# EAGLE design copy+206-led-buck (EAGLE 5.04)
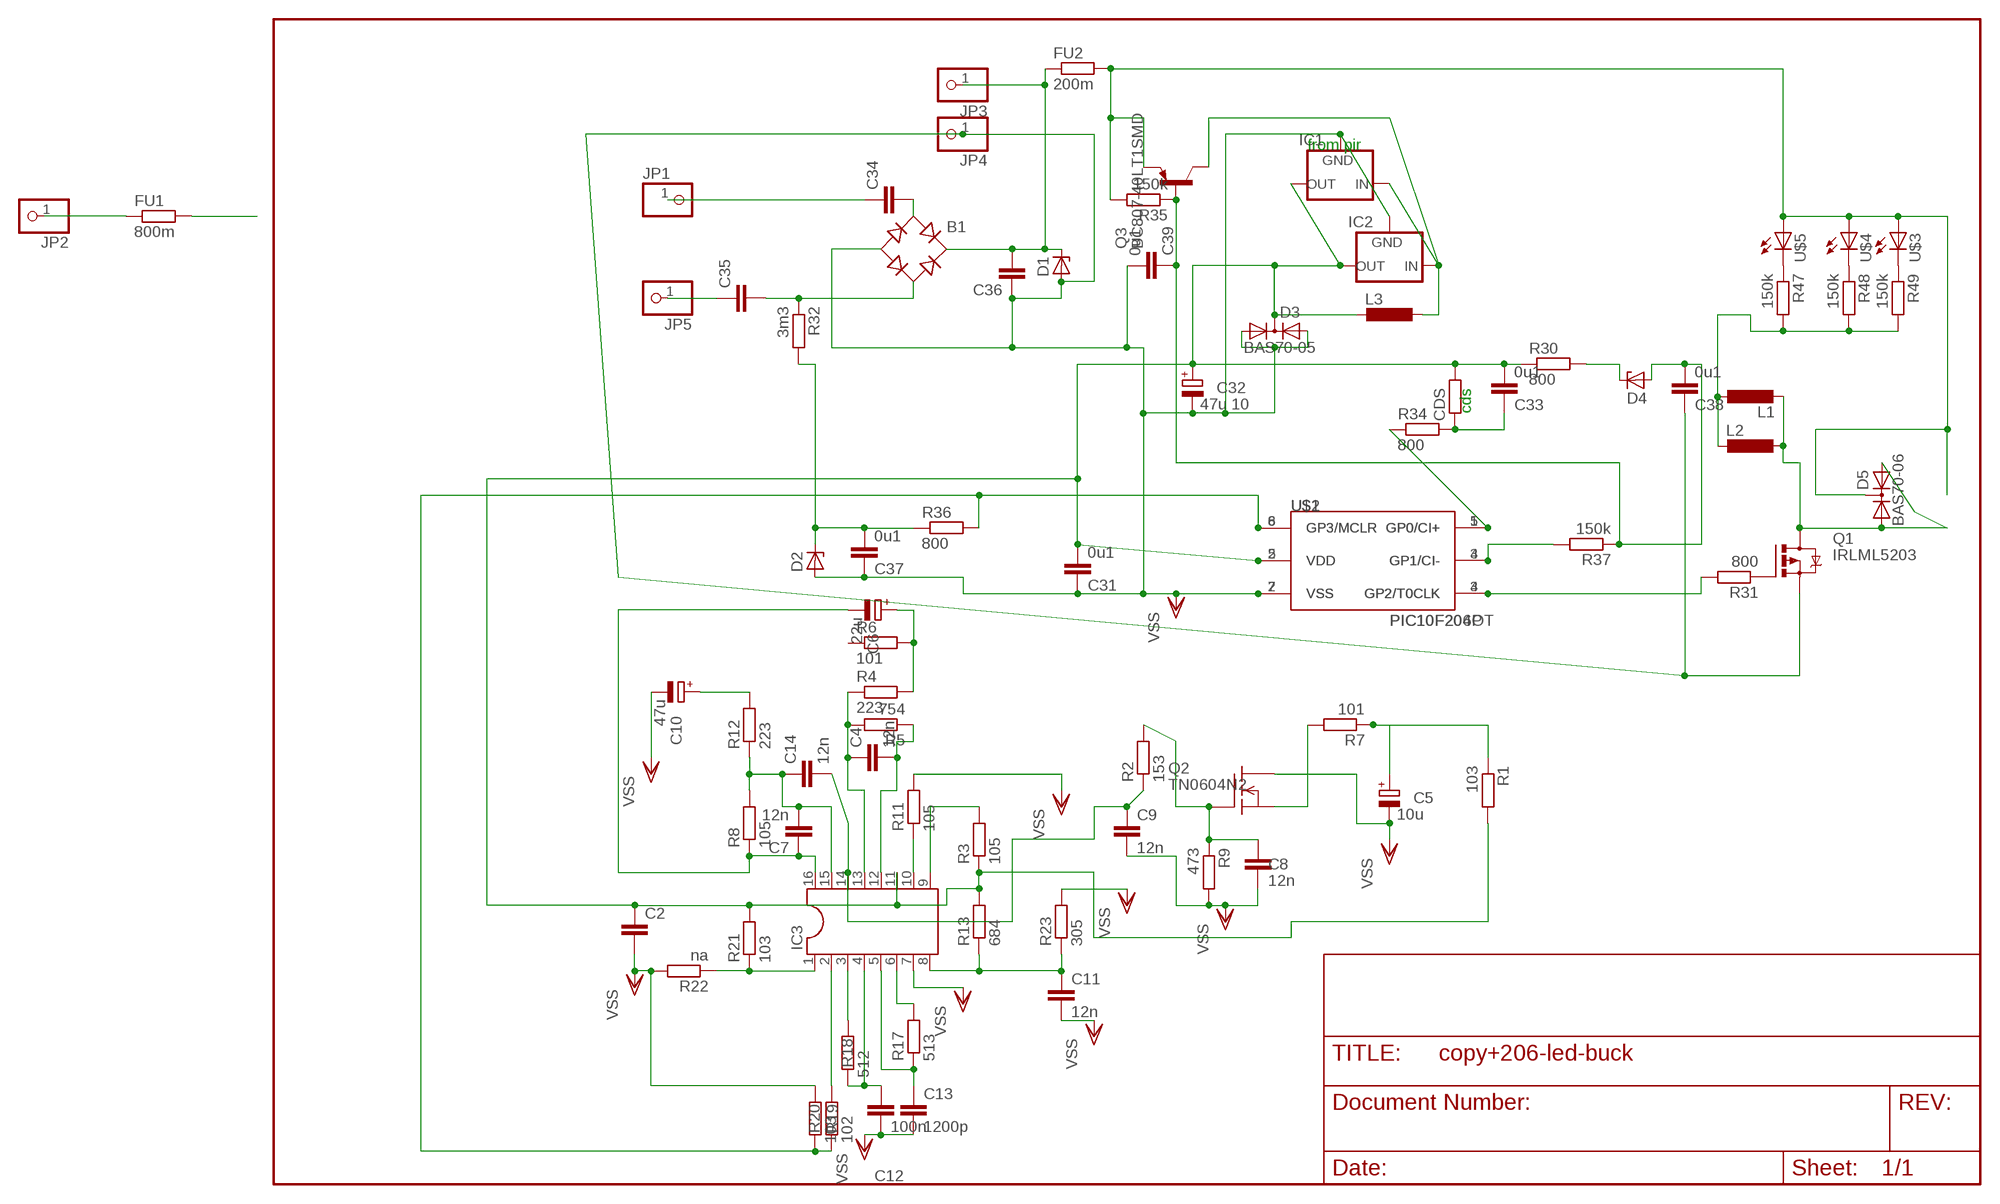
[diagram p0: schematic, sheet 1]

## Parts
B1  RB1A  [RB1A]
C2  C-EUC0805  [C0805]
C4  12n  C-EUC0805  [C0805]
C5  10u  CPOL-EUE2.5-5  [E2,5-5]
C6  22u  CPOL-EUE2.5-5  [E2,5-5]
C7  12n  C-EUC0805  [C0805]
C8  12n  C-EUC0805  [C0805]
C9  12n  C-EUC0805  [C0805]
C10  47u  CPOL-EUE2.5-5  [E2,5-5]
C11  12n  C-EUC0805  [C0805]
C12  100n  C-EUC0805  [C0805]
C13  1200p  C-EUC0805  [C0805]
C14  12n  C-EUC0805  [C0805]
C31  0u1  C-EUC1206  [C1206]
C32  47u 10  CPOL-EUE2.5-5  [E2,5-5]
C33  0u1  C-EUC1206  [C1206]
C34  C-EU050-025X075  [C050-025X075]
C35  C-EU050-025X075  [C050-025X075]
C36  C-EU050-025X075  [C050-025X075]
C37  0u1  C-EUC1206  [C1206]
C38  0u1  C-EUC1206  [C1206]
C39  0u1  C-EUC1206  [C1206]
CDS  R-EU_0207/5V  [0207/5V]
D1  ZENER-DIODEZD-7.5  [ZDIO-7.5]
D2  ZENER-DIODESOT23  [SOT23]
D3  BAS70-05  [SOT23]
D4  ZENER-DIODESOT23  [SOT23]
D5  BAS70-06  [SOT23]
FU1  800m  R-EU_0204/5  [0204/5]
FU2  200m  R-EU_0204/5  [0204/5]
IC1  XC63FPT  [TO92]
IC2  XC63FPP  [SOT89R]
IC3  DIL16SO16  [SO16]
JP1  PINHD-1X1  [1X01]
JP2  PINHD-1X1  [1X01]
JP3  PINHD-1X1  [1X01]
JP4  PINHD-1X1  [1X01]
JP5  PINHD-1X1  [1X01]
L1  L-EUL5650M  [L5650M]
L2  L-EU0207/7  [0207/7]
L3  L-EU0204V  [0204V]
Q1  IRLML5203  [MICRO3]
Q2  TN0604N2  [TO-39]
Q3  BC807-40LT1SMD  [SOT23-BEC]
R1  103  R-EU_R0805  [R0805]
R2  153  R-EU_R0805  [R0805]
R3  105  R-EU_R0805  [R0805]
R4  223  R-EU_R0805  [R0805]
R5  754  R-EU_R0805  [R0805]
R6  101  R-EU_R0805  [R0805]
R7  101  R-EU_R0805  [R0805]
R8  105  R-EU_R0805  [R0805]
R9  473  R-EU_R0805  [R0805]
R11  105  R-EU_R0805  [R0805]
R12  223  R-EU_R0805  [R0805]
R13  684  R-EU_R0805  [R0805]
R17  513  R-EU_R0805  [R0805]
R18  512  R-EU_R0805  [R0805]
R19  102  R-EU_R0805  [R0805]
R20  103  R-EU_R0805  [R0805]
R21  103  R-EU_R0805  [R0805]
R22  na  R-EU_R0805  [R0805]
R23  305  R-EU_R0805  [R0805]
R30  800  R-EU_R1206  [R1206]
R31  800  R-EU_R1206  [R1206]
R32  3m3  R-EU_R1206  [R1206]
R34  800  R-EU_R1206  [R1206]
R35  150k  R-EU_R0805  [R0805]
R36  800  R-EU_R1206  [R1206]
R37  150k  R-EU_R1206  [R1206]
R47  150k  R-EU_R1206  [R1206]
R48  150k  R-EU_R1206  [R1206]
R49  150k  R-EU_R1206  [R1206]
U$1  PIC10F206P  [DIL8]
U$2  PIC10F204OT  [SOT23-6]
U$3  LED5MM  [LED5MM]
U$4  LED5MM  [LED5MM]
U$5  LED5MM  [LED5MM]

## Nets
N$1: B1.+ C36.2 D1.C FU2.1 JP3.1
N$4: FU1.1 JP2.1
N$6: D4.3(C) R30.2
N$7: D5.3(C) FU2.2 Q3.E R35.2 U$3.A U$4.A U$5.A
N$8: C38.2 C39.1 D4.1(A) Q3.B R35.1 R37.1
N$9: FU1.2
N$10: Q1.1(G) R31.1
N$11: IC3.1 R21.1 R22.1
N$12: R19.1 R20.1 R36.2 U$1.8(GP3/MCLR) U$2.6(GP3/MCLR)
N$13: R37.2 U$1.4(GP1/CI-) U$2.3(GP1/CI-)
N$14: R31.2 U$1.3(GP2/T0CLK) U$2.4(GP2/T0CLK)
N$15: IC1.2(IN) IC2.2(IN) L3.1 Q3.C
N$16: C37.2 D2.3(C) R32.2 R36.1
N$17: C35.1 JP5.1
N$18: B1.AC2 C35.2 R32.1
N$20: C34.1 JP1.1
N$22: L1.1 L2.2 R47.2 R48.2 R49.2
N$23: C33.1 CDS.1 R34.2
N$24: IC3.2 R19.2
N$25: C12.1 IC3.4 R18.1
N$26: D5.1(A1) D5.2(A2) L1.2 L2.1 Q1.3(D)
N$27: IC3.3 R18.2
N$28: C11.1 IC3.8 R13.1 R23.1
N$29: R34.1 U$1.5(GP0/CI+) U$2.1(GP0/CI+)
N$30: C13.1 IC3.5 R17.1
N$31: IC3.6 R17.2
N$32: IC3.10 R11.1
N$33: B1.AC1 C34.2
N$34: C4.2 IC3.12 R5.1
N$35: C4.1 IC3.13 R4.1 R5.2
N$36: IC3.9 R3.2
N$37: C6.+ R4.2 R6.2
N$38: R47.1 U$5.K(C)
N$39: C9.1 C14.2 IC3.14 R2.1
N$40: C7.2 C14.1 IC3.15 R8.2 R12.1
N$41: C6.- C7.1 IC3.16 R8.1
N$42: Q2.1(S) R7.2
N$43: C5.+ R1.1 R7.1
N$44: C10.+ R12.2
N$46: C8.1 Q2.2(G) R2.2 R9.1
N$54: R48.1 U$4.K(C)
N$55: R49.1 U$3.K(C)
V2CC: C2.1 C31.2 C32.+ C33.2 CDS.2 D3.3(C) IC1.3(OUT) IC2.3(OUT) IC3.11 L3.2 R1.2 R3.1 R13.2 R21.2 R30.1 U$1.2(VDD) U$2.5(VDD)
VSS: B1.- C2.2 C5.- C8.2 C9.2 C10.- C11.2 C12.2 C13.2 C31.1 C32.- C36.1 C37.1 C38.1 C39.2 D1.A D2.1(A) D3.1(A1) D3.2(A2) IC1.1(GND) IC2.1(GND) IC3.7 JP4.1 Q1.2(S) Q2.3(D) R9.2 R11.2 R20.2 R22.2 R23.2 U$1.7(VSS) U$2.2(VSS)
Unconnected: R6.1

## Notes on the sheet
- from pir
- cds

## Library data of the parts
B1 = rectifier:RB1A: RECTIFIER 1 A
C2 C4 C7-C9 C11-C14 = rcl-2:C-EU: CAPACITOR, European symbol
C5 C6 C10 C32 = rcl:CPOL-EU: POLARIZED CAPACITOR, European symbol
C31 C33-C39 = rcl:C-EU: CAPACITOR, European symbol
CDS = rcl(2):R-EU_: RESISTOR, European symbol
D1 D2 D4 = diode-1:ZENER-DIODE: Z-Diode
D3 = diode-1:BAS70-05: Silicon Schottky Diodes General-purpose diode for high-speed switching
D5 = diode-1:BAS70-06: Silicon Schottky Diodes General-purpose diode for high-speed switching
FU1 FU2 R30-R32 R34-R37 R47-R49 = rcl:R-EU_: RESISTOR, European symbol
IC1 IC2 = v-reg:XC63FP: Positiv Voltage Regulators www.torex.co.jp/english/product/pro02/pdf/0201_xc62fp.pdf
IC3 = ic-package:DIL16: Dual In Line / Socket
JP1-JP5 = pinhead:PINHD-1X1: PIN HEADER
L1 = rcl-2:L-EU: INDUCTOR, European symbol
L2 L3 = rcl:L-EU: INDUCTOR, European symbol
Q1 = transistor-power:IRLML5203: HEXFET P-Channel Power MOSFET
Q2 = transistor-fet:TN0604N2: N-Channel Enhancement MOSFET 40V; 4A; 0,85Ohm
Q3 = transistor-pnp:BC807*: PNP Transistror
R1-R9 R11-R13 R17-R23 = rcl-2:R-EU_: RESISTOR, European symbol
U$1 U$2 = microchip-3:PIC10F2*: uPC nW 0,25/0,5k Program Flash memory Comparator
U$3-U$5 = led(3):LED: LED

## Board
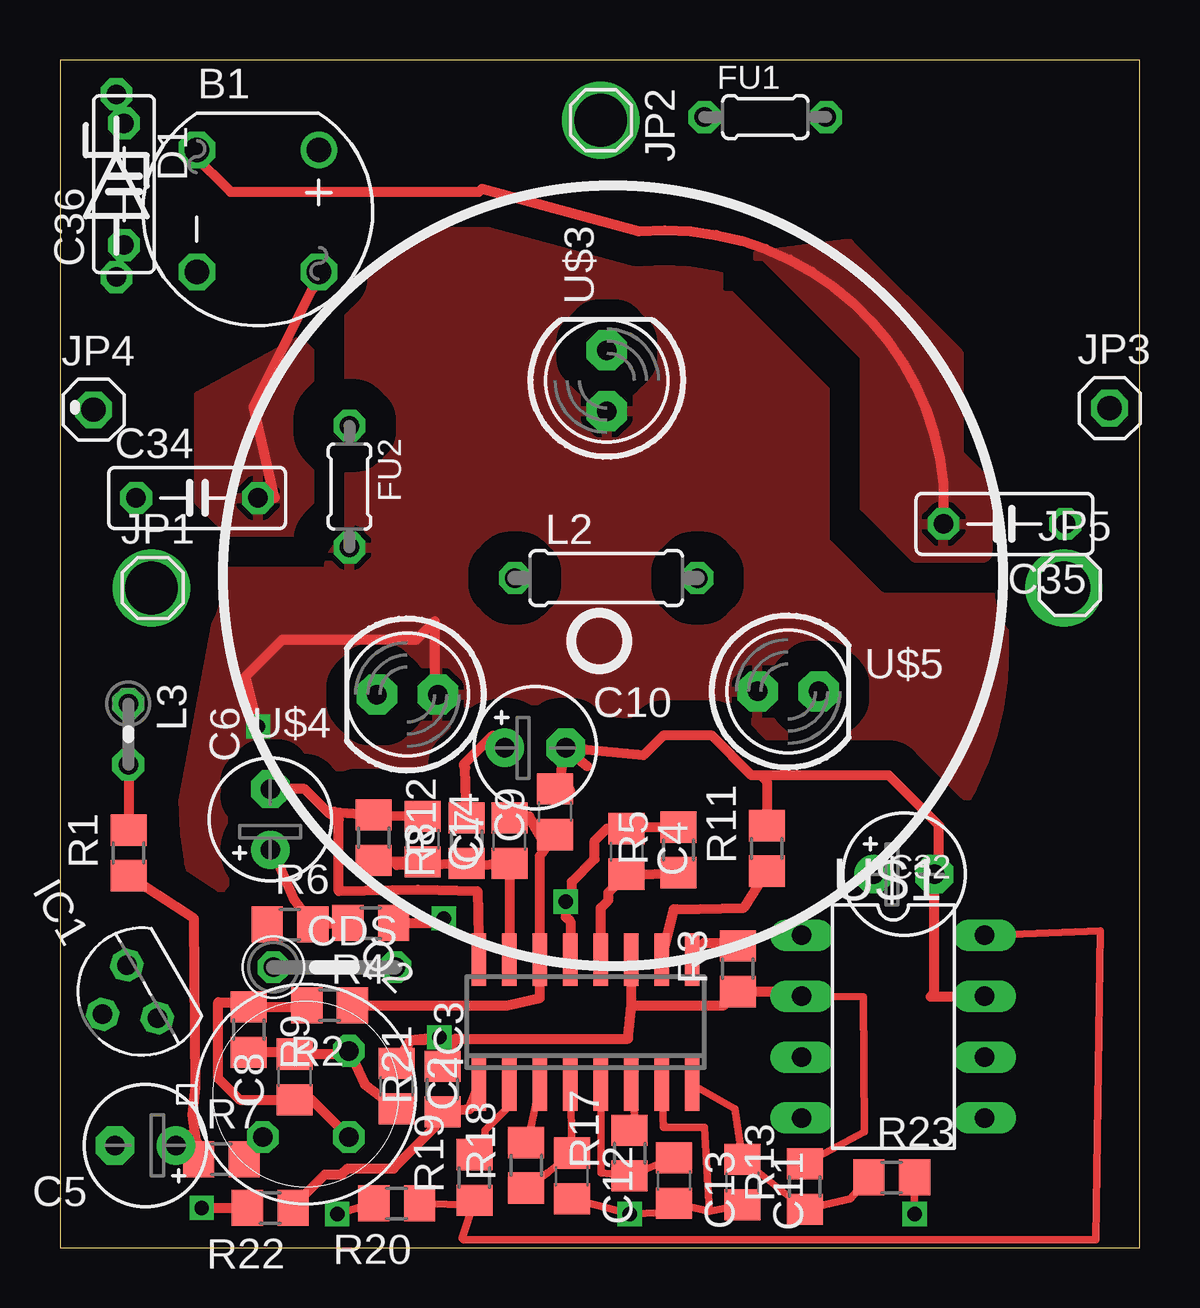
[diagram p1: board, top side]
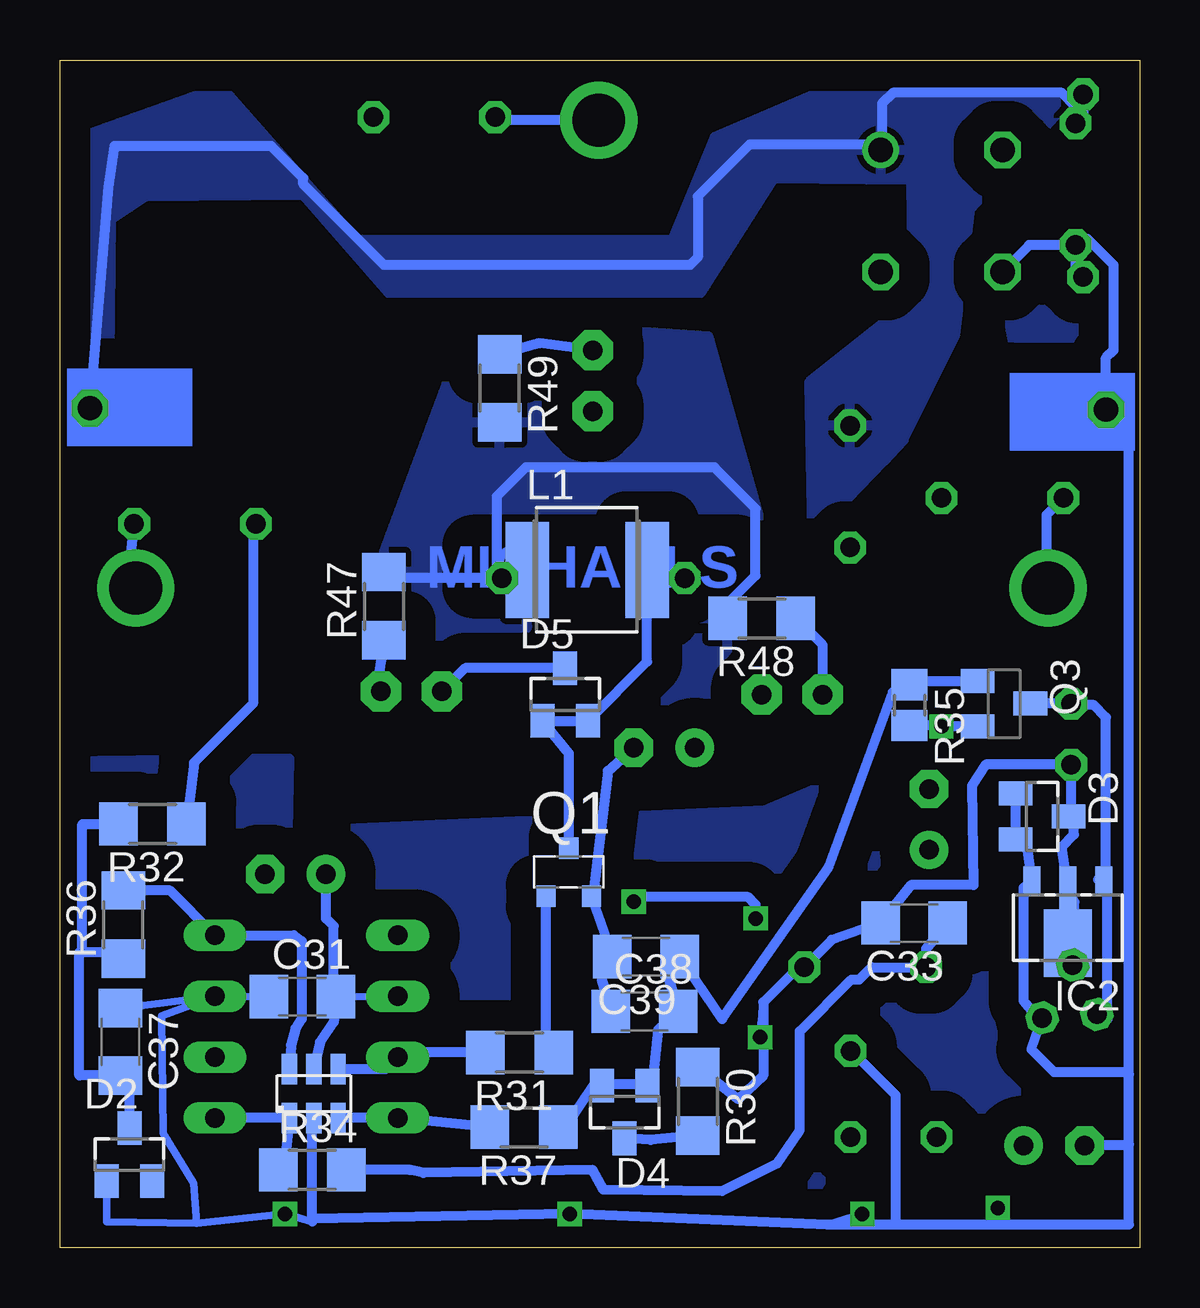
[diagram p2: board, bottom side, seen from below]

Size 45 x 49.5 mm. Coordinates in mm from the lower left corner, seen from the top.
Outline: 0,0 45,0 45,49.5 0,49.5 0,0
Copper layers (1*16): Top 0.035mm / dielectric 1.5mm / Bottom 0.035mm
Design rules "default": minimum track width 10mil, minimum drill 24mil, track to track 8mil, track to pad 8mil, pad to pad 8mil, via to via 8mil, smd to smd 8mil, copper to edge 40mil, drill to drill 8mil, minimum pad ring 10mil, minimum via ring 8mil, stop-mask expansion 4mil, vias tented up to drill 0mil, thermal gap 10mil

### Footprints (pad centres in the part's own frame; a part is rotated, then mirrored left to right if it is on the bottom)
RB1A = drill 1.016 round: + -2.54,2.54 | drill 1.016 octagon: - 2.54,-2.54; AC1 2.54,2.54; AC2 -2.54,-2.54
C0805 = smd 1.3 x 1.5: 1 -0.95,0; 2 0.95,0
E2,5-5 = drill 0.813 pad 1.6 round: + -1.27,0 | drill 0.813 pad 1.6 octagon: - 1.27,0
C1206 = smd 1.6 x 1.8: 1 -1.4,0; 2 1.4,0
C050-025X075 = drill 0.813 octagon: 1 -2.54,0; 2 2.54,0
0207/5V = drill 0.813 octagon: 1 -2.54,0; 2 2.54,0
ZDIO-7.5 = drill 0.813 octagon: A 3.81,0; C -3.81,0
SOT23 = smd 1 x 1.4: 1 -0.95,-1.1; 2 0.95,-1.1; 3 0,1.1
0204/5 = drill 0.813 octagon: 1 -2.54,0; 2 2.54,0
TO92 = drill 0.813 octagon: 1 -1.27,0; 2 0,1.905; 3 1.27,0
SOT89R = smd 0.7 x 1.1: 1 1.5,-1.75; 2 -1.5,-1.75 | smd 0.7 x 1.8: 3 0,-1.4 | smd 2 x 2.8: 4 0,0.9
SO16 = smd 0.6 x 2.2: 1 -4.445,-2.6; 2 -3.175,-2.6; 3 -1.905,-2.6; 4 -0.635,-2.6; 5 0.635,-2.6; 6 1.905,-2.6; 7 3.175,-2.6; 8 4.445,-2.6; 9 4.445,2.6; 10 3.175,2.6; 11 1.905,2.6; 12 0.635,2.6; 13 -0.635,2.6; 14 -1.905,2.6; 15 -3.175,2.6; 16 -4.445,2.6
1X01 = drill 1.016 octagon: 1 0,0
L5650M = smd 1.8 x 4: 1 -2.5,0; 2 2.5,0
0207/7 = drill 0.813 octagon: 1 -3.81,0; 2 3.81,0
0204V = drill 0.813 octagon: 1 -1.27,0; 2 1.27,0
MICRO3 = smd 0.8 x 0.9: 1 -0.95,-1; 2 0.95,-1; 3 0,1
TO-39 = drill 0.813 octagon: 1 0,-2.54; 2 2.54,0; 3 0,2.54
SOT23-BEC = smd 1 x 1.4: B -0.95,-1.1; C 0,1.1; E 0.95,-1.1
R0805 = smd 1.3 x 1.5: 1 -0.95,0; 2 0.95,0
R1206 = smd 1.6 x 1.803: 1 -1.422,0; 2 1.422,0
R0805' = smd 1.3 x 1.5: 1 -0.85,0; 2 0.85,0
DIL8 = drill 0.813 long: 1 -3.81,-3.81; 2 -1.27,-3.81; 3 1.27,-3.81; 4 3.81,-3.81; 5 3.81,3.81; 6 1.27,3.81; 7 -1.27,3.81; 8 -3.81,3.81
SOT23-6 = smd 0.635 x 1.27: 1 -1.016,-1.016; 2 0,-1.016; 3 1.016,-1.016; 4 1.016,1.016; 5 0,1.016; 6 -1.016,1.016
LED5MM = drill 0.813 pad 1.676 octagon: A -1.27,0; K 1.27,0

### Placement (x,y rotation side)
B1  8.25,43.21 270 top
C2  14.03,6.73 270 top
C4  23.62,16.51 270 top
C5  3.56,4.25 180 top
C6  8.76,17.84 90 top
C7  15.11,17.02 270 top
C8  9.78,7.11 90 top
C9  20.64,18.16 90 top
C10  19.81,20.83 0 top
C11  28.45,2.73 270 top
C12  21.34,2.98 270 top
C13  25.59,2.79 270 top
C14  18.73,16.95 90 top
C31  34.89,10.46 0 bottom
C32  35.18,15.56 0 top
C33  9.4,13.53 180 bottom
C34  5.71,31.24 0 top
C35  39.37,30.16 180 top
C36  2.67,44.32 90 top
C37  42.48,8.57 270 bottom
C38  20.64,9.84 0 bottom
C39  20.57,12.13 180 bottom
CDS  11.43,11.68 0 top
D1  2.35,44.26 270 top
D2  42.1,3.87 0 bottom
D3  4.06,17.97 270 bottom
D4  21.46,5.65 180 bottom
D5  23.94,23.05 0 bottom
FU1  29.4,47.12 0 top
FU2  12.07,31.72 270 top
IC1  3.42,10.67 120 top
IC2  2.98,13.59 180 bottom
IC3  21.91,9.4 0 top
JP1  3.87,27.5 0 top
JP2  22.54,46.99 270 top
JP3  43.75,34.99 0 top
JP4  1.4,34.92 0 top
JP5  42.1,27.62 0 top
L1  23.02,28.25 0 bottom
L2  22.77,27.91 0 top
L3  2.85,21.4 270 top
Q1  23.79,15.65 0 bottom
Q2  10.25,6.4 315 top
Q3  5.65,22.67 270 bottom
R1  2.86,16.45 90 top
R2  11.24,10.1 180 top
R3  28.26,11.62 90 top
R4  12.95,13.53 180 top
R5  25.78,16.57 90 top
R6  9.59,13.46 0 top
R7  6.73,3.68 0 top
R8  13.08,17.08 270 top
R9  7.87,9.08 270 top
R11  29.46,16.64 90 top
R12  16.95,16.95 90 top
R13  31.05,2.54 90 top
R17  23.75,3.94 90 top
R18  19.43,3.43 90 top
R19  17.27,2.92 90 top
R20  14.03,1.84 180 top
R21  15.94,6.6 90 top
R22  8.76,1.65 180 top
R23  34.67,2.92 0 top
R30  18.41,6.1 270 bottom
R31  25.84,8.13 180 bottom
R32  41.15,17.65 180 bottom
R34  34.48,3.24 0 bottom
R35  150k  [R0805']  9.59,22.61 270 bottom
R36  42.35,13.46 90 bottom
R37  25.65,5.02 180 bottom
R47  31.5,26.73 90 bottom
R48  15.75,26.23 180 bottom
R49  26.67,35.81 270 bottom
U$1  34.73,9.21 270 top
U$2  34.42,6.41 0 bottom
U$3  22.8,36.13 90 top
U$4  14.48,23.05 180 top
U$5  30.35,23.18 0 top

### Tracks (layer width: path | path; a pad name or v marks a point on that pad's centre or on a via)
GND
  pour Bottom (isolate 1.27, rank 5): 0.95,42.93 6.22,42.8 5.21,37.27 1.91,33.02 1.78,22.61 5.78,22.42 15.62,18.22 35.5,17.34 35.43,20.38 45.02,20.26 44.64,0.32 -0.06,0.25
N$1
  Bottom 0.406: JP3.1 42.99,44.2 42.74,45.91 36.2,45.91 34.86,44.58 34.86,44.32 31.5,40.96 18.73,40.96 18.41,41.27 18.41,43.81 16.26,45.97 11.2,45.97 B1.+ 10.73,45.8 10.73,47.69 10.29,48.13 3.24,48.13 2.67,47.56 C36.2 2.35,47.18 D1.C
  pour Bottom (isolate 1.27, rank 2): 1.52,49.34 9.97,49.59 17.72,46.29 19.49,42 32.64,42 38.29,48.39 44.89,46.04 44.7,36.96 42.93,37.08 42.86,42.86 41.4,43.81 34.86,43.88 31.31,39.8 18.29,39.8 15.24,44.58 9.53,44.51 9.46,39.5 13.78,36.07 13.65,29.65 10.67,32.77 9.84,33.66 7.68,38.04 7.05,43.31
N$2  (via drill 2.2)
  other vias: 3.81,27.5
N$3  (via drill 2.2)
  other vias: 41.85,27.5
N$4
  Bottom 0.406: JP2.1 26.73,46.99 FU1.1
N$5  (via drill 2.2)
  other vias: 22.54,46.99
N$6
  Bottom 0.406: R30.2 20.38,4.48 D4.3
N$7  (via drill 0.6)
  Top 0.406: v8.26,21.72 7.75,23.81 9.27,25.34 14.86,25.34 15.62,26.1 15.62,23.18 U$4.A
  Bottom 0.406: D5.3 28.11,24.15 U$5.A | Q3.E 6.79,21.72 v8.26,21.72 8.29,21.76 R35.2
  pour Top (isolate 1.27, rank 3): 21.97,43.56 arc90 6.99,28.57 5.14,18.61 arc90 19.18,4.57 26.54,12.06 arc90 39.37,24.89 39.37,29.02 arc90 24.64,43.75 22.23,43.75
N$8
  Bottom 0.406: R37.1 23.94,5.02 22.73,6.79 20.53,6.79 D4.1 20.32,6.92 20.26,7.3 20.07,9.08 C38.2 19.62,11.18 C39.1 17.4,9.53 12.95,15.88 10.29,23.14 R35.1 9.43,23.62 Q3.B
N$10
  Bottom 0.406: R31.1 24.74,8.13 Q1.1
N$11
  Top 0.406: IC3.1 17.08,5.78 R21.1 15.62,5.34 15.62,5.02 13.91,3.3 12,3.3 11.75,3.05 11.05,3.05 9.71,1.71 R22.1
N$12
  Top 0.305: R20.1 16.7,1.78 R19.1 16.76,0.38 16.83,0.32 43.18,0.32 43.37,13.21 U$1.8
  Bottom 0.406: U$1.8 35.24,13.02 34.92,12.76 34.92,9.53 35.18,9.14 35.37,8.45 U$2.6 | U$1.8 39.41,12.64 | R36.2 40.41,14.88 U$1.8
N$13
  Bottom 0.406: R37.2 U$1.4 U$2.3
N$14
  Bottom 0.406: U$2.4 31.43,7.43 U$1.3 30.92,8.13 R31.2 27.2,7.56
N$15
  Bottom 0.406: IC1.2 1.58,9.34 1.33,9.53 1.33,14.93 IC2.2 1.74,15.34 1.4,15.68 1.4,22.1 1.91,22.61 2.78,22.61 L3.1 Q3.C
N$16
  Bottom 0.406: 44.07,12.32 44.2,12.32 44.2,7.17 C37.2 42.1,6.79 D2.3 | 44.07,12.32 42.35,12.32 R36.1 | R32.2 44.07,17.65 44.07,12.32
N$17
  Bottom 0.406: JP5.1 42.1,28.32 C35.1
N$18
  Top 0.406: B1.AC2 5.52,45.6 7.11,44.01 17.46,44.01 17.59,44.13 24.13,42.35 arc-90 36.83,31.81 C35.2
  Bottom 0.406: R32.1 39.41,20.22 36.96,22.67 36.96,30.04 C35.2
  pour Top (isolate 0.61): 29.02,41.34 29.34,41.34 33.53,37.15 33.53,30.86 35.62,28.77 38.54,28.77 38.67,28.89 38.67,31.88 37.47,33.08 37.47,37.27 32.89,41.85
N$20
  Bottom 0.406: JP1.1 3.87,30.54 C34.1
N$22
  Bottom 0.406: L2.2 31.25,27.91 R47.2 | R48.2 17.17,26.84 16,28 16,30.8 17.72,32.51 25.59,32.51 26.8,31.3 26.8,28.13 L2.2 | L1.1 26.23,28.25 L2.2
  pour Bottom (isolate 1.27, rank 2): 21.97,38.29 28.07,38.23 36,16.95 12.19,17.4 17.97,37.97 21.59,38.23
N$23
  Bottom 0.406: C33.1 8.89,12.45 CDS.1 11.18,11.68 11.68,11.18 12,11.18 14.16,9.02 14.16,4.89 15.11,3.49 17.4,2.35 22.35,2.41 22.8,3.24 29.84,3.11 30.42,3.24 R34.2
N$24
  Top 0.305: IC3.2 18.61,5.78 17.72,4.89 17.72,4.63 R19.2
N$25
  Top 0.305: IC3.4 C12.1 20.32,3.11 R18.1
N$26
  Bottom 0.406: Q1.3 23.79,20.6 D5.1 D5.2 20.52,24.42 L1.2 20.18,27.91 L2.1
N$27
  Top 0.305: IC3.3 19.62,4.95 R18.2
N$28
  Top 0.305: IC3.8 28.13,5.78 C11.1 R13.1 32.96,2.03 R23.1
N$29
  Bottom 0.406: U$1.5 U$2.1 35.69,3.2 R34.1
N$30
  Top 0.305: IC3.5 22.54,3.11 R17.1 C13.1
N$31
  Top 0.305: IC3.6 23.94,5.52 23.88,5.08 23.37,4.76 R17.2
N$32
  Top 0.406: IC3.10 25.59,14.1 25.72,14.1 28.51,14.16 R11.1
N$33
  Top 0.406: C34.2 8.95,31.24 8.06,35.05 10.54,39.96 B1.AC1
  pour Top (isolate 1.676): 5.78,35.5 5.78,31.11 7.05,29.84 9.84,29.84 10.41,30.42 10.41,37.34 9.97,37.78
N$34
  Top 0.406: IC3.12 22.54,14.16 22.86,14.48 22.86,14.8 C4.2 24.26,15.56 R5.1
N$35  (via drill 0.6)
  Top 0.406: R4.1 15.81,13.53 v16,13.72 | IC3.13 21.27,13.59 21.08,13.78 v21.08,14.41 21.34,14.67 21.34,15.24 22.29,16.19 22.29,16.95 22.79,17.46 23.11,17.46 | 23.11,17.46 C4.1 | R5.2 23.18,17.52 23.11,17.46
  Bottom 0.406: v16,13.72 16,14.29 16.32,14.61 20.89,14.61 v21.08,14.41
N$36
  Top 0.406: IC3.9 26.35,12.19 26.86,12.7 28.13,12.7 R3.2
N$37
  Top 0.406: R4.2 R6.2 9.78,14.48 9.02,16.26 9.21,16.45 C6.+
N$38
  Bottom 0.406: U$5.K 31.81,23.18 R47.1
N$39
  Top 0.406: R2.1 18.63,10.09 20,10.4 IC3.14 20,16.32 C9.1 20.07,17.08 19.56,17.97 19.05,17.65 C14.2
N$40
  Top 0.406: R8.2 C7.2 14.03,15.94 R12.1 16.39,15.62 16.45,15.62 17.46,15.94 C14.1 IC3.15
N$41
  Top 0.406: IC3.16 17.4,14.86 14.92,14.92 11.62,14.86 11.62,17.84 11.21,18.11 | 11.21,18.11 11.43,18.16 R8.1 C7.1 | C6.- 10.21,19.11 11.21,18.11
N$42
  Top 0.305: Q2.1 R7.2
N$43
  Top 0.406: R1.1 5.59,13.72 5.65,6.67 5.53,5.53 R7.1 5.78,4.25 5.52,4.7 4.83,4.7 C5.+
N$44
  Top 0.406: C10.+ 18.03,21.34 16.83,20.13 16.89,20 R12.2
N$46
  Top 0.406: R2.2 10.22,10.03 R9.1 7.68,10.22 6.6,10.22 6.6,7.05 7.49,6.16 C8.1 10.49,6.16 Q2.2
N$54
  Bottom 0.406: 13.27,22.99 U$4.K 13.21,25.11 R48.1
N$55
  Bottom 0.406: U$3.K 25.02,37.69 R49.1
V2CC  (via drill 0.6)
  Top 0.305: R13.2 33.53,4.83 C31.2 U$1.2
  Top 0.406: 23.81,10.1 IC3.11 | 23.81,10.1 23.69,8.7 16.51,8.7 | 14.6,8.64 16.51,8.7 | 14.6,8.64 C2.1 | R21.2 16.13,8.13 16.51,8.7 | 23.81,10.1 27.68,10.1 R3.1 30.73,10.67 U$1.2 | R1.2 2.86,20.12 L3.2 | v15.81,8.76 14.6,8.64
  Bottom 0.305: U$1.2 C31.2
  Bottom 0.406: U$2.5 34.16,8.57 33.59,9.4 33.53,9.85 C31.2 33.59,10.55 33.59,13.4 33.91,13.72 C32.+ | IC1.3 2.71,14.4 IC2.3 3.24,16.7 2.73,17.21 2.73,17.74 D3.3 2.85,18.09 L3.2 6.41,20.13 6.99,19.24 6.92,15.11 9.53,15.11 C33.2 12.83,12.82 CDS.2 14.22,11.68 15.68,10.22 15.68,9.84 | R30.1 16.74,6.18 15.68,7.18 15.68,9.84 | 15.68,9.84 v15.81,8.76
VSS  (via drill 0.6)
  Top 0.305: v11.56,1.4 R20.2 | 27.07,1.52 C13.2 25.12,1.46 v23.75,1.4 C12.2 | 27.07,1.52 C11.2 | IC3.7 25.15,5.02 26.86,5.02 27.07,1.52 | v35.62,1.4 R23.2
  Top 0.406: C2.2 12.7,6.8 Q2.3 11.91,8.06 C8.2 9.71,8.13 R9.2 | v5.91,1.65 R22.2 | C10.- 24.32,20.51 25.15,21.34 27.18,21.34 28.83,19.68 29.21,19.68 | C9.2 21.27,19.05 20.89,19.43 20.89,19.88 C10.- | U$1.7 38.52,10.46 C31.1 36.45,10.61 C32.- 36.64,15.75 36.64,17.59 34.54,19.68 29.21,19.68 | R11.2 29.46,19.43 29.21,19.68 | C10.- 21.97,20.07
  Bottom 0.305: 13.02,0.95 v11.56,1.4 | 34.48,1.08 v35.62,1.4 39.31,1.02 | U$1.7 C31.1 | U$1.7 C37.1 | U$1.7 40.77,9.65 40.7,4.76 39.43,2.67 39.31,1.02 | D2.1 43.05,1.08 39.31,1.02
  Bottom 0.406: U$2.2 34.48,5.4 34.48,1.21 | 34.48,1.08 34.48,1.21 | 5.91,0.95 0.45,0.95 0.45,4.32 | 5.91,0.95 10.16,0.95 | 10.16,0.95 13.02,0.95 v23.75,1.4 34.48,1.21 | 0.45,4.32 0.45,7.24 | 0.45,7.24 0.45,34.04 1.4,34.04 JP4.1 1.4,37.08 1.08,37.4 1.08,40.96 2.16,42.04 2.41,42.04 C36.1 | D3.1 D3.2 4.74,17.15 IC2.1 4.83,15 4.83,10.29 4.51,9.91 IC1.1 4.51,8.26 3.56,7.3 0.51,7.3 0.45,7.24 | C5.- 0.51,4.25 0.45,4.32 | Q2.3 12.01,8.2 10.16,6.35 10.16,0.95 | 5.91,0.95 v5.91,1.65 | C38.1 22.42,11.18 C39.2 22.8,14.48 | 22.8,14.48 Q1.2 | 22.8,14.48 22.16,19.87 C10.- | C36.1 4.59,41.78 B1.- | C36.1 2.67,41.91 | C36.1 2.67,40.77 D1.A
(copper drawn outside any net)
  shapes: Bottom area x2

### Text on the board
Bottom: MICHAELS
